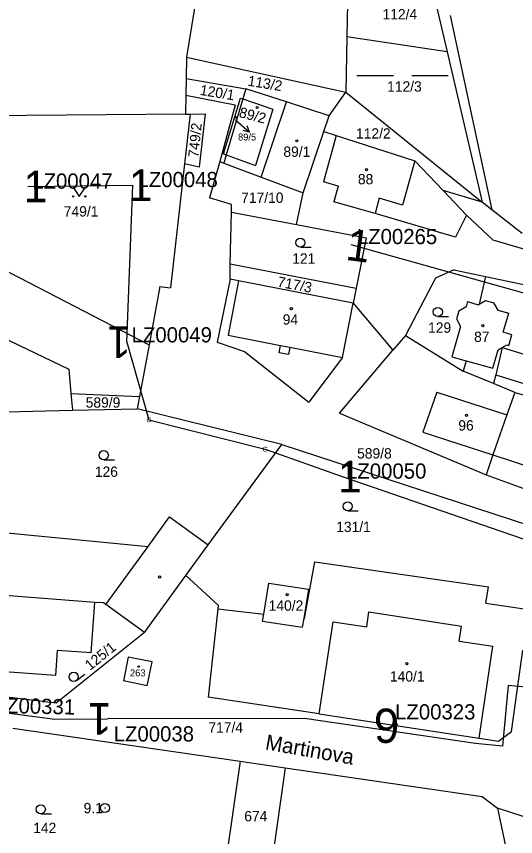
# Model space of a CAD drawing. Extents: x -738131 to -734179, y -1033447 to -1030078.
# Drawn here: x -736048.4 to -735966.3, y -1032166.9 to -1032032.1 of the extents above; entities that cross this region are included whole.
import ezdxf

# ---------------------------------------------------------------- set-up
doc = ezdxf.new("R2010")
doc.units = 0
for name, color, linetype in [('ftf_2010', 7, 'Continuous'), ('ftf_2050', 7, 'Continuous'), ('ftf_2080', 7, 'Continuous'), ('ftf_3010', 7, 'Continuous'), ('ftf_3010_ftf_3010_gtda_3015_gtda_3015_1', 7, 'Continuous'), ('ftf_3050', 7, 'Continuous'), ('ftf_3050_ftf_3050_gtda_3055_gtda_3055_1', 7, 'Continuous'), ('ftf_3240', 7, 'Continuous'), ('ftf_nu', 7, 'Continuous'), ('Vrstva 1', 7, 'Continuous'), ('Vrstva 2', 7, 'Continuous'), ('Vrstva 3', 7, 'Continuous'), ('Vrstva 4', 7, 'Continuous'), ('Vrstva 5', 7, 'Continuous'), ('Vrstva 7', 7, 'Continuous'), ('Vrstva 8', 7, 'Continuous')]:
    doc.layers.add(name, color=color, linetype=linetype)

msp = doc.modelspace()

# ---------------------------------------------------------------- linework, layer by layer
at = {"layer": 'ftf_2010'}
for points in [[(-736046.5, -1032060.06), (-736029.23, -1032059.86)], [(-736030.22, -1032085.66), (-736029.23, -1032059.86)], [(-736084.14, -1032136.1), (-736083.63, -1032137.03), (-736061.14, -1032145.09), (-736042.04, -1032147.61), (-736033.38, -1032147.59)], [(-735958.39, -1032137.2), (-735958.85, -1032137.46), (-735959.94, -1032142.82), (-735967.55, -1032142.1), (-735968.5, -1032152.08), (-735972.92, -1032151.65), (-736001.05, -1032147.52), (-736033.38, -1032147.59)], [(-735986.08, -1032148.72), (-735986.48, -1032148.45), (-735985.68, -1032148.45), (-735986.08, -1032148.72)]]:
    msp.add_lwpolyline(points, dxfattribs=at)
at = {"layer": 'ftf_2050'}
msp.add_lwpolyline([(-735993.42, -1032069.62), (-735957.23, -1032079.77), (-735920.9, -1032093.01)], dxfattribs=at)
at = {"layer": 'ftf_2080'}
for points in [[(-736030.22, -1032085.66), (-736026.59, -1032098.41), (-736007.51, -1032103.26), (-735994.86, -1032107.74)], [(-735994.86, -1032107.74), (-735963.7, -1032118.48), (-735954.07, -1032124.91)]]:
    msp.add_lwpolyline(points, dxfattribs=at)
at = {"layer": 'Vrstva 1'}
for points in [[(-736014.98, -1032005.52), (-736020.41, -1032038.84)], [(-735993.84, -1032024.39), (-735994.05, -1032035.48)], [(-735980.21, -1032026.72), (-735977.6, -1032037.92)], [(-735994.05, -1032035.48), (-735994.23, -1032044.56)], [(-735977.6, -1032037.92), (-735994.05, -1032035.48)], [(-735977.6, -1032037.92), (-735971.83, -1032062.67)], [(-736020.41, -1032038.84), (-736020.47, -1032042.32)], [(-736020.41, -1032038.84), (-735994.23, -1032044.56)], [(-736020.47, -1032042.32), (-736020.52, -1032045.14)], [(-736020.47, -1032042.32), (-736010.65, -1032044)], [(-736010.65, -1032044), (-736011.15, -1032045.68)], [(-736003.96, -1032046.16), (-736010.65, -1032044)], [(-736020.52, -1032045.14), (-736020.57, -1032048.19)], [(-736012.39, -1032046.69), (-736020.52, -1032045.14)], [(-736014.35, -1032054.73), (-736011.53, -1032045.55)], [(-736011.53, -1032045.55), (-736011.15, -1032045.68)], [(-735996.96, -1032048.43), (-735994.23, -1032044.56)], [(-735994.23, -1032044.56), (-735971.83, -1032062.67)], [(-736012.39, -1032046.69), (-736014.96, -1032055.98)], [(-736011.15, -1032045.68), (-736013.9, -1032054.89)], [(-736011.15, -1032045.68), (-736006.23, -1032047.36)], [(-735996.96, -1032048.43), (-736003.96, -1032046.16)], [(-736020.57, -1032048.19), (-736059.91, -1032048.52)], [(-736019.82, -1032048.18), (-736020.75, -1032056.33)], [(-736020.57, -1032048.19), (-736019.82, -1032048.18)], [(-736019.82, -1032048.18), (-736017.32, -1032048.15)], [(-736017.32, -1032048.15), (-736018.31, -1032056.89)], [(-736006.23, -1032047.36), (-736009.08, -1032056.63)], [(-735997.84, -1032051.05), (-735996.96, -1032048.43)], [(-736001.22, -1032061.11), (-735997.84, -1032051.05)], [(-735995.84, -1032051.69), (-735997.92, -1032059.33)], [(-735997.84, -1032051.05), (-735995.84, -1032051.69)], [(-735995.84, -1032051.69), (-735982.91, -1032055.83)], [(-736014.35, -1032054.73), (-736013.9, -1032054.89)], [(-736013.9, -1032054.89), (-736014.3, -1032056.22)], [(-736013.9, -1032054.89), (-736009.08, -1032056.63)], [(-736020.75, -1032056.33), (-736023.06, -1032076.71)], [(-736018.31, -1032056.89), (-736020.75, -1032056.33)], [(-736014.96, -1032055.98), (-736016.62, -1032061.96)], [(-736014.71, -1032056.07), (-736014.96, -1032055.98)], [(-736014.71, -1032056.07), (-736014.3, -1032056.22)], [(-736014.3, -1032056.22), (-736008.12, -1032058.53)], [(-735978.26, -1032060.71), (-735982.91, -1032055.83)], [(-736008.12, -1032058.53), (-736001.22, -1032061.11)], [(-735995.5, -1032060.04), (-735997.92, -1032059.33)], [(-735995.5, -1032060.04), (-735996.19, -1032062.57)], [(-736002.35, -1032066.34), (-736001.22, -1032061.11)], [(-735971.83, -1032062.67), (-735978.26, -1032060.71)], [(-735974.39, -1032064.76), (-735978.26, -1032060.71)], [(-736013.02, -1032063.04), (-736016.62, -1032061.96)], [(-736013.04, -1032064.3), (-736013.02, -1032063.04)], [(-735989.44, -1032064.53), (-735996.19, -1032062.57)], [(-735970.22, -1032063.93), (-735971.83, -1032062.67)], [(-736013.21, -1032072.78), (-736013.04, -1032064.3)], [(-736013.04, -1032064.3), (-736002.35, -1032066.34)], [(-735965.25, -1032067.79), (-735970.22, -1032063.93)], [(-735976.22, -1032068.38), (-735989.44, -1032064.53)], [(-735974.39, -1032064.76), (-735976.22, -1032068.38)], [(-735970.01, -1032068.9), (-735974.39, -1032064.76)], [(-736002.35, -1032066.34), (-735990.87, -1032068.53)], [(-736058.61, -1032069.51), (-736026.55, -1032086.09)], [(-735990.87, -1032068.53), (-735992.54, -1032076.81)], [(-735929.85, -1032080.72), (-735970.01, -1032068.9)], [(-736013.26, -1032075.3), (-736013.21, -1032072.78)], [(-736013.21, -1032072.78), (-735992.54, -1032076.81)], [(-735976.5, -1032073.75), (-735979.49, -1032075.16)], [(-735976.5, -1032073.75), (-735971.27, -1032074.85)], [(-735979.49, -1032075.16), (-735984.45, -1032084.56)], [(-735971.27, -1032074.85), (-735972.32, -1032079.4)], [(-735971.27, -1032074.85), (-735960.54, -1032077.11)], [(-736024.77, -1032076.49), (-736026.55, -1032086.09)], [(-736024.77, -1032076.49), (-736023.06, -1032076.71)], [(-736013.26, -1032075.3), (-736015.38, -1032085.68)], [(-736011.84, -1032075.58), (-736013.26, -1032075.3)], [(-735993.03, -1032079.26), (-736011.84, -1032075.58)], [(-735992.54, -1032076.81), (-735993.03, -1032079.26)], [(-735994.78, -1032088.2), (-735993.03, -1032079.26)], [(-735993.03, -1032079.26), (-735986.51, -1032086.99)], [(-735974.27, -1032079), (-735974.45, -1032079.85)], [(-735974.27, -1032079), (-735972.49, -1032079.5)], [(-735975.69, -1032080.56), (-735976.05, -1032081.84)], [(-735974.45, -1032079.85), (-735975.69, -1032080.56)], [(-735972.49, -1032079.5), (-735972.32, -1032079.4)], [(-735976.05, -1032081.84), (-735975.37, -1032083.08)], [(-736056.43, -1032082.12), (-736039.76, -1032090.12)], [(-735975.37, -1032083.08), (-735976.8, -1032088.05)], [(-735984.45, -1032084.56), (-735986.51, -1032086.99)], [(-735984.45, -1032084.56), (-735974.93, -1032090.41)], [(-736015.38, -1032085.68), (-736010.89, -1032087.21)], [(-736026.55, -1032086.09), (-736028.13, -1032094.58)], [(-736010.89, -1032087.21), (-736000.29, -1032095.53)], [(-735995.29, -1032097.33), (-735986.51, -1032086.99)], [(-735968.53, -1032086.54), (-735969.6, -1032091.01)], [(-735968.53, -1032086.54), (-735963.34, -1032088.11)], [(-735994.78, -1032088.2), (-736000.29, -1032095.53)], [(-735976.8, -1032088.05), (-735974.47, -1032088.71)], [(-735974.47, -1032088.71), (-735974.93, -1032090.41)], [(-736039.76, -1032090.12), (-736039.39, -1032094.1)], [(-735969.95, -1032092.48), (-735974.93, -1032090.41)], [(-735969.6, -1032091.01), (-735969.95, -1032092.48)], [(-735966.46, -1032093.93), (-735969.95, -1032092.48)], [(-736039.39, -1032094.1), (-736039.13, -1032096.86)], [(-736039.39, -1032094.1), (-736028.13, -1032094.58)], [(-735966.46, -1032093.93), (-735967.76, -1032097.63)], [(-735966.46, -1032093.93), (-735963.36, -1032094.79)], [(-736028.13, -1032094.58), (-736028.5, -1032096.6)], [(-736039.13, -1032096.86), (-736028.5, -1032096.6)], [(-736004.74, -1032102.47), (-736028.5, -1032096.6)], [(-736056.61, -1032097.28), (-736039.13, -1032096.86)], [(-735995.29, -1032097.33), (-735971.2, -1032107.47)], [(-735967.76, -1032097.63), (-735970.06, -1032104.2)], [(-736016.85, -1032118.96), (-736004.74, -1032102.47)], [(-736004.74, -1032102.47), (-735961.21, -1032116.72)], [(-735970.06, -1032104.2), (-735971.2, -1032107.47)], [(-735971.2, -1032107.47), (-735960.32, -1032111.44)], [(-736026.73, -1032119.25), (-736023.2, -1032114.37)], [(-736023.2, -1032114.37), (-736016.85, -1032118.96)], [(-736055.04, -1032116.5), (-736026.73, -1032119.25)], [(-736020.52, -1032124.03), (-736016.85, -1032118.96)], [(-736001, -1032131.11), (-735999.3, -1032121.76)], [(-735999.3, -1032121.76), (-735970.78, -1032125.89)], [(-736027.29, -1032133.39), (-736020.52, -1032124.03)], [(-736015.22, -1032128.91), (-736020.52, -1032124.03)], [(-736007.73, -1032130.35), (-736006.91, -1032125.3)], [(-736006.91, -1032125.3), (-736000.38, -1032126.28)], [(-736000.38, -1032126.28), (-736001.16, -1032131.09)], [(-735971.26, -1032128.56), (-735970.78, -1032125.89)], [(-736036.09, -1032136.75), (-736035.46, -1032128.43)], [(-736034.04, -1032128.51), (-736035.46, -1032128.43)], [(-736033.64, -1032128.8), (-736034.04, -1032128.51)], [(-736027.29, -1032133.39), (-736033.64, -1032128.8)], [(-736015.22, -1032128.91), (-736015.28, -1032129.51)], [(-735971.26, -1032128.56), (-735963.82, -1032129.64)], [(-736015.28, -1032129.51), (-736016.86, -1032144.02)], [(-736015.28, -1032129.51), (-736007.73, -1032130.35)], [(-736007.92, -1032131.52), (-736007.73, -1032130.35)], [(-736007.92, -1032131.52), (-736001.39, -1032132.49)], [(-736001.16, -1032131.09), (-736001.39, -1032132.49)], [(-736001.16, -1032131.09), (-736001, -1032131.11)], [(-736027.29, -1032133.39), (-736041.81, -1032145.03)], [(-736041.89, -1032140.47), (-736041.58, -1032136.33)], [(-736036.09, -1032136.75), (-736041.58, -1032136.33)], [(-735966.99, -1032149.64), (-735965.16, -1032136.3)], [(-736029.98, -1032137.42), (-736030.77, -1032141.34)], [(-736026.06, -1032138.21), (-736029.98, -1032137.42)], [(-736026.85, -1032142.13), (-736026.06, -1032138.21)], [(-736041.89, -1032140.47), (-736050.28, -1032139.83)], [(-736026.85, -1032142.13), (-736030.77, -1032141.34)], [(-736041.81, -1032145.03), (-736050.38, -1032143.98)], [(-735998.63, -1032146.78), (-736016.86, -1032144.02)], [(-735998.63, -1032146.78), (-735972.32, -1032150.76)], [(-736048.93, -1032149.09), (-736011.61, -1032154.54)], [(-735969.13, -1032151.24), (-735966.99, -1032149.64)], [(-735972.32, -1032150.76), (-735969.13, -1032151.24)], [(-736011.61, -1032154.54), (-736013.85, -1032170.14)], [(-736011.61, -1032154.54), (-736004.18, -1032155.62)], [(-736004.18, -1032155.62), (-736006.37, -1032171.16)], [(-736004.18, -1032155.62), (-735971.86, -1032160.34)], [(-735971.86, -1032160.34), (-735969.32, -1032162.27)], [(-735959, -1032165.61), (-735969.32, -1032162.27)], [(-735969.32, -1032162.27), (-735939.26, -1032305.31)]]:
    msp.add_lwpolyline(points, dxfattribs=at)
at = {"layer": 'Vrstva 3'}
for p, q in [((-735992.4, -1032041.84), (-735986.4, -1032041.84)), ((-735983.4, -1032041.84), (-735977.4, -1032041.84)), ((-736001.7, -1032070.07), (-735999.95, -1032070.07)), ((-735979.12, -1032081.45), (-735977.37, -1032081.45)), ((-736034, -1032104.99), (-736032.25, -1032104.99)), ((-735993.93, -1032113.4), (-735992.18, -1032113.4)), ((-736038.5, -1032141.28), (-736037.11, -1032140.21)), ((-736044.35, -1032163.22), (-736042.6, -1032163.22))]:
    msp.add_line(p, q, dxfattribs=at)
msp.add_lwpolyline([(-736039.02, -1032060.19), (-736038.02, -1032061.69), (-736037.02, -1032060.19)], dxfattribs=at)
for centre, radius in [((-736039.02, -1032061.69), 0.1), ((-736037.02, -1032061.69), 0.1), ((-736001.7, -1032069.32), 0.75), ((-735979.12, -1032080.7), 0.75), ((-736034, -1032104.24), 0.75), ((-735993.93, -1032112.65), 0.75), ((-736038.96, -1032140.68), 0.75), ((-736044.35, -1032162.47), 0.75)]:
    msp.add_circle(centre, radius, dxfattribs=at)
at = {"layer": 'Vrstva 4'}
for points in [[(-735977.09, -1032031.96), (-735970.22, -1032063.93)], [(-736008.12, -1032058.53), (-736003.96, -1032046.16)], [(-735982.91, -1032055.83), (-735984.9, -1032063.12)], [(-735988.74, -1032062), (-735989.44, -1032064.53)], [(-735984.9, -1032063.12), (-735988.74, -1032062)], [(-736011.84, -1032075.58), (-736013.59, -1032084.52)], [(-735972.32, -1032079.4), (-735971.29, -1032078.81)], [(-735971.29, -1032078.81), (-735969.95, -1032079.18)], [(-735969.95, -1032079.18), (-735969.24, -1032080.41)], [(-735969.24, -1032080.41), (-735967.47, -1032080.89)], [(-735968.38, -1032084.02), (-735967.47, -1032080.89)], [(-736013.59, -1032084.52), (-736004.95, -1032086.21)], [(-735966.96, -1032084.44), (-735968.38, -1032084.02)], [(-735967.46, -1032086.21), (-735966.96, -1032084.44)], [(-736005.18, -1032087.39), (-736004.95, -1032086.21)], [(-736004.95, -1032086.21), (-736003.42, -1032086.51)], [(-736003.42, -1032086.51), (-736003.65, -1032087.69)], [(-736003.42, -1032086.51), (-735994.78, -1032088.2)], [(-735970.1, -1032089.94), (-735969.23, -1032086.94)], [(-735969.23, -1032086.94), (-735968.53, -1032086.54)], [(-735968.53, -1032086.54), (-735967.81, -1032086.12)], [(-735967.81, -1032086.12), (-735967.46, -1032086.21)], [(-736003.65, -1032087.69), (-736005.18, -1032087.39)], [(-735974.47, -1032088.71), (-735970.1, -1032089.94)], [(-735969.6, -1032091.01), (-735958.08, -1032094.59)], [(-735979.27, -1032093.89), (-735981.56, -1032100.45)], [(-735979.27, -1032093.89), (-735967.76, -1032097.63)], [(-735981.56, -1032100.45), (-735970.06, -1032104.2)], [(-735970.06, -1032104.2), (-735960.21, -1032107.4)], [(-736033.64, -1032128.8), (-736026.73, -1032119.25)], [(-736035.46, -1032128.43), (-736061.48, -1032126.45)], [(-735990.8, -1032132.48), (-735990.43, -1032129.98)], [(-735990.43, -1032129.98), (-735975.24, -1032132.32)], [(-735998.63, -1032146.78), (-735996.29, -1032131.64)], [(-735996.29, -1032131.64), (-735990.8, -1032132.48)], [(-735975.61, -1032134.81), (-735975.24, -1032132.32)], [(-735975.61, -1032134.81), (-735970.1, -1032135.66)], [(-735972.32, -1032150.76), (-735970.1, -1032135.66)]]:
    msp.add_lwpolyline(points, dxfattribs=at)
at = {"layer": 'Vrstva 5'}
for centre, radius in [((-736008.8, -1032047.1), 0.175), ((-736012.3, -1032048.72), 0.117), ((-736002.29, -1032052.57), 0.175), ((-735990.83, -1032057.31), 0.175), ((-736003.18, -1032080.15), 0.175), ((-735971.72, -1032082.96), 0.175), ((-735974.4, -1032097.69), 0.175), ((-736024.83, -1032124.26), 0.175), ((-736003.88, -1032127.17), 0.175), ((-735984.22, -1032138.51), 0.175), ((-736028.25, -1032138.98), 0.117)]:
    msp.add_circle(centre, radius, dxfattribs=at)
at = {"layer": 'Vrstva 7'}
for p, q in [((-736012.29, -1032049.15), (-736010.04, -1032051.14)), ((-736010.04, -1032051.14), (-736011.12, -1032050.85)), ((-736010.04, -1032051.14), (-736010.46, -1032050.1))]:
    msp.add_line(p, q, dxfattribs=at)
msp.add_lwpolyline([(-736012.38, -1032049.07), (-736012.29, -1032049.15)], dxfattribs=at)
at = {"layer": 'Vrstva 8'}
for radius in [0.75, 0.03]:
    msp.add_circle((-736033.8, -1032162.24), radius, dxfattribs=at)

# ---------------------------------------------------------------- texts
at = {"layer": 'ftf_3010'}
for p in [(-736047.15, -1032062.66), (-736029.88, -1032062.46), (-735995.51, -1032110.34)]:
    msp.add_text('1', height=5.2, dxfattribs=at).set_placement(p)
for rotation, p in [(352.4844, (-735994.4, -1032072.11)), (180, (-736029.58, -1032083.06)), (180, (-736032.73, -1032144.99))]:
    msp.add_text('1', height=5.2, rotation=rotation, dxfattribs=at).set_placement(p)
at = {"layer": 'ftf_3010_ftf_3010_gtda_3015_gtda_3015_1'}
for s, p in [('LZ00048', (-736028.46, -1032060.18)), ('LZ00047', (-736045.75, -1032060.43)), ('LZ00265', (-735992.42, -1032069.55)), ('LZ00050', (-735994.2, -1032108.1))]:
    msp.add_text(s, height=2.5, dxfattribs=at).set_placement(p)
for s, rotation, p in [('LZ00049', 0, (-736029.43, -1032085.7)), ('LZ00331', 358.7101, (-736051.93, -1032146.59)), ('LZ00038', 0, (-736032.37, -1032151.3))]:
    msp.add_text(s, height=2.5, rotation=rotation, dxfattribs=at).set_placement(p)
at = {"layer": 'ftf_3050'}
msp.add_text('6', height=5.63, rotation=180, dxfattribs=at).set_placement((-735985.43, -1032145.9))
at = {"layer": 'ftf_3050_ftf_3050_gtda_3055_gtda_3055_1'}
msp.add_text('LZ00323', height=2.5, rotation=0, dxfattribs=at).set_placement((-735986.14, -1032147.68))
at = {"layer": 'ftf_3240'}
for p in [(-736026.99, -1032098.81), (-736007.91, -1032103.66)]:
    msp.add_text('G', height=0.8, dxfattribs=at).set_placement(p)
at = {"layer": 'ftf_nu'}
msp.add_text('Martinova', height=2.5, rotation=350, dxfattribs=at).set_placement((-736007.59, -1032152.59))
at = {"layer": 'Vrstva 2'}
for s, height, p in [('112/4', 1.7, (-735988.21, -1032032.61)), ('112/3', 1.7, (-735987.45, -1032044.48)), ('89/5', 0.1, (-736012.53, -1032049.07)), ('112/2', 1.7, (-735992.56, -1032052.2)), ('89/1', 1.7, (-736004.49, -1032055.2)), ('88', 1.7, (-735992.25, -1032059.72)), ('717/10', 1.7, (-736011.43, -1032062.76)), ('749/1', 1.7, (-736040.57, -1032065.01)), ('121', 1.7, (-736003.04, -1032072.76)), ('94', 1.7, (-736004.6, -1032082.78)), ('129', 1.7, (-735980.72, -1032084.12)), ('87', 1.7, (-735973.16, -1032085.63)), ('589/9', 1.7, (-736036.97, -1032096.43)), ('96', 1.7, (-735975.75, -1032100.19)), ('589/8', 1.7, (-735992.38, -1032104.79)), ('126', 1.7, (-736035.47, -1032107.8)), ('131/1', 1.7, (-735995.82, -1032116.87)), ('140/2', 1.7, (-736006.91, -1032129.81)), ('263', 1.14, (-736029.69, -1032140.6)), ('140/1', 1.7, (-735986.99, -1032141.45)), ('717/4', 1.7, (-736016.81, -1032149.85)), ('674', 1.7, (-736010.92, -1032164.43)), ('142', 1.7, (-736045.6, -1032166.37))]:
    msp.add_text(s, height=height, dxfattribs=at).set_placement(p)
for s, rotation, p in [('113/2', 350.665, (-736010.44, -1032043.49)), ('120/1', 350.7539, (-736018.29, -1032045)), ('89/2', 345.2819, (-736011.9, -1032048.63)), ('749/2', 84.3976, (-736018.45, -1032055.36)), ('717/3', 349.4761, (-736005.57, -1032076.52)), ('125/1', 39.1321, (-736036.24, -1032139.7))]:
    msp.add_text(s, height=1.7, rotation=rotation, dxfattribs=at).set_placement(p)
at = {"layer": 'Vrstva 7'}
msp.add_text('89/5', height=1.14, dxfattribs=at).set_placement((-736011.94, -1032052.51))
at = {"layer": 'Vrstva 8'}
msp.add_text('9.1', height=1.7, dxfattribs=at).set_placement((-736037.31, -1032163.09))

doc.saveas('drawing.dxf')
